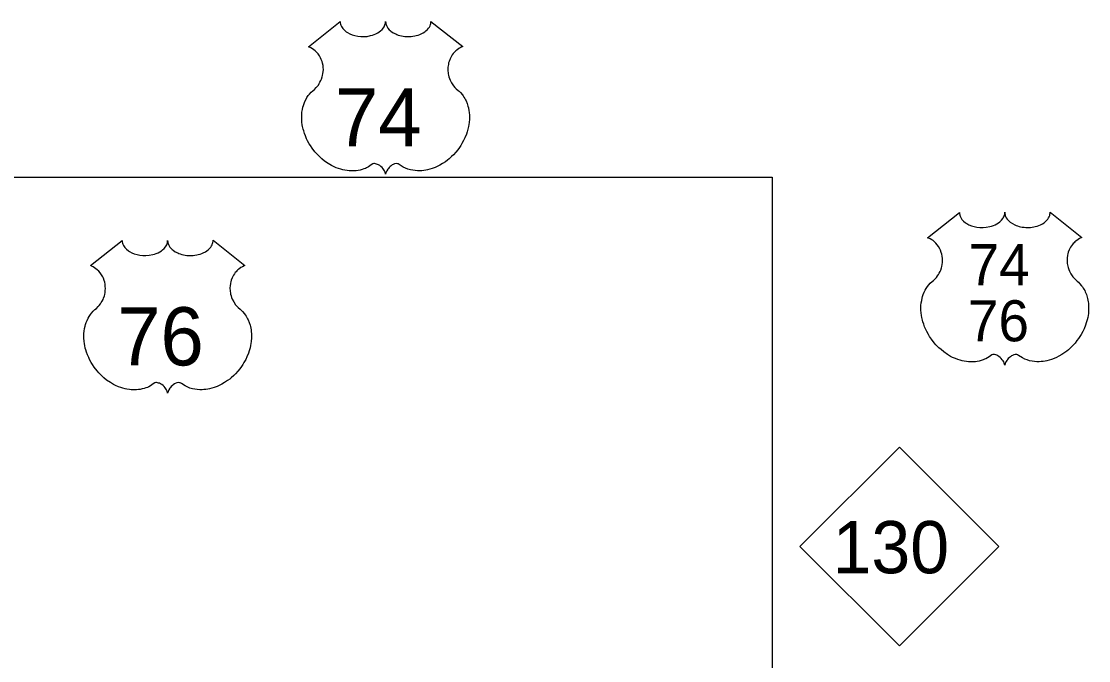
# Model space of a CAD drawing. Extents: x 5197761 to 5514561, y 1890130 to 2080942.
# Drawn here: x 5282925 to 5297224, y 2011870 to 2020438 of the extents above; entities that cross this region are included whole.
import ezdxf

# ---------------------------------------------------------------- set-up
doc = ezdxf.new("R2010")
doc.units = 0
for name, color, linetype in [('Exist Road Primary NC Shield CELL', 7, 'Continuous'), ('Exist Road Primary NC Shield Number Label', 7, 'Continuous'), ('Exist Road Primary US Shield CELL', 7, 'Continuous'), ('Exist Road Primary US Shield Number Label', 7, 'Continuous'), ('Map Preparation Inset Cut Line', 7, 'Continuous')]:
    doc.layers.add(name, color=color, linetype=linetype)

msp = doc.modelspace()

# ---------------------------------------------------------------- linework, layer by layer
at = {"layer": 'Exist Road Primary NC Shield CELL'}
msp.add_lwpolyline([(5293356, 2013399), (5294688, 2014731), (5296020, 2013399), (5294688, 2012067)], close=True, dxfattribs=at)
at = {"layer": 'Exist Road Primary US Shield CELL'}
for points in [[(5287197, 2020437), (5287198, 2020419), (5287202, 2020399), (5287205, 2020388), (5287215, 2020367), (5287231, 2020343), (5287254, 2020319), (5287279, 2020298), (5287296, 2020287), (5287325, 2020271), (5287358, 2020258), (5287395, 2020247), (5287432, 2020240), (5287473, 2020235), (5287513, 2020234), (5287557, 2020237), (5287605, 2020247), (5287628, 2020253), (5287652, 2020261), (5287676, 2020271), (5287701, 2020284), (5287721, 2020297), (5287737, 2020309), (5287760, 2020330), (5287778, 2020353), (5287785, 2020365), (5287792, 2020377), (5287801, 2020403), (5287803, 2020414), (5287805, 2020438), (5287806, 2020418), (5287808, 2020406), (5287812, 2020394), (5287817, 2020381), (5287826, 2020363), (5287836, 2020348), (5287855, 2020325), (5287867, 2020314), (5287877, 2020306), (5287906, 2020286), (5287940, 2020269), (5287957, 2020261), (5287974, 2020255), (5287995, 2020249), (5288018, 2020244), (5288040, 2020240), (5288062, 2020236), (5288085, 2020235), (5288104, 2020234), (5288127, 2020234), (5288149, 2020236), (5288171, 2020238), (5288195, 2020242), (5288214, 2020247), (5288240, 2020253), (5288263, 2020262), (5288283, 2020270), (5288309, 2020284), (5288331, 2020298), (5288346, 2020310), (5288365, 2020327), (5288382, 2020348), (5288393, 2020362), (5288400, 2020378), (5288407, 2020394), (5288411, 2020411), (5288413, 2020426), (5288413, 2020438), (5288838, 2020100), (5288828, 2020096), (5288805, 2020085), (5288787, 2020074), (5288758, 2020053), (5288745, 2020042), (5288733, 2020030), (5288721, 2020017), (5288711, 2020006), (5288699, 2019989), (5288688, 2019971), (5288677, 2019953), (5288669, 2019936), (5288656, 2019902), (5288650, 2019881), (5288646, 2019862), (5288641, 2019824), (5288639, 2019806), (5288639, 2019788), (5288640, 2019770), (5288642, 2019751), (5288645, 2019733), (5288648, 2019716), (5288654, 2019696), (5288661, 2019672), (5288670, 2019649), (5288690, 2019612), (5288715, 2019575), (5288733, 2019553), (5288750, 2019535), (5288776, 2019513), (5288791, 2019501), (5288807, 2019484), (5288834, 2019454), (5288844, 2019439), (5288855, 2019423), (5288865, 2019406), (5288875, 2019388), (5288883, 2019372), (5288898, 2019335), (5288909, 2019300), (5288914, 2019281), (5288922, 2019240), (5288925, 2019219), (5288928, 2019178), (5288929, 2019129), (5288925, 2019082), (5288916, 2019028), (5288909, 2018995), (5288898, 2018957), (5288887, 2018924), (5288867, 2018876), (5288850, 2018841), (5288828, 2018800), (5288812, 2018775), (5288795, 2018748), (5288772, 2018717), (5288746, 2018685), (5288715, 2018650), (5288689, 2018625), (5288656, 2018595), (5288636, 2018579), (5288608, 2018557), (5288568, 2018531), (5288530, 2018509), (5288497, 2018492), (5288468, 2018479), (5288430, 2018465), (5288367, 2018448), (5288345, 2018443), (5288317, 2018439), (5288292, 2018436), (5288267, 2018435), (5288234, 2018435), (5288201, 2018437), (5288170, 2018442), (5288138, 2018449), (5288104, 2018459), (5288073, 2018471), (5288042, 2018486), (5287989, 2018519), (5287974, 2018527), (5287966, 2018530), (5287945, 2018531), (5287926, 2018527), (5287907, 2018519), (5287895, 2018513), (5287879, 2018502), (5287867, 2018493), (5287853, 2018479), (5287843, 2018467), (5287835, 2018458), (5287820, 2018435), (5287815, 2018424), (5287809, 2018410), (5287805, 2018388), (5287798, 2018415), (5287790, 2018433), (5287781, 2018448), (5287772, 2018461), (5287757, 2018478), (5287743, 2018491), (5287727, 2018504), (5287710, 2018514), (5287697, 2018521), (5287684, 2018526), (5287669, 2018530), (5287656, 2018531), (5287646, 2018531), (5287632, 2018527), (5287613, 2018514), (5287594, 2018501), (5287574, 2018489), (5287551, 2018476), (5287534, 2018468), (5287513, 2018460), (5287489, 2018452), (5287463, 2018445), (5287436, 2018440), (5287412, 2018436), (5287387, 2018434), (5287364, 2018433), (5287340, 2018433), (5287318, 2018435), (5287292, 2018437), (5287260, 2018442), (5287233, 2018448), (5287205, 2018456), (5287176, 2018465), (5287145, 2018477), (5287107, 2018493), (5287080, 2018507), (5287037, 2018532), (5286988, 2018566), (5286950, 2018596), (5286923, 2018621), (5286882, 2018662), (5286859, 2018689), (5286821, 2018738), (5286797, 2018773), (5286782, 2018798), (5286759, 2018839), (5286747, 2018865), (5286731, 2018903), (5286718, 2018937), (5286708, 2018970), (5286702, 2018991), (5286694, 2019027), (5286689, 2019053), (5286684, 2019089), (5286682, 2019126), (5286681, 2019160), (5286682, 2019189), (5286685, 2019222), (5286691, 2019258), (5286698, 2019288), (5286704, 2019310), (5286713, 2019337), (5286725, 2019366), (5286739, 2019394), (5286752, 2019418), (5286769, 2019443), (5286786, 2019464), (5286808, 2019488), (5286830, 2019509), (5286851, 2019526), (5286875, 2019550), (5286888, 2019565), (5286904, 2019585), (5286916, 2019604), (5286926, 2019621), (5286939, 2019646), (5286946, 2019664), (5286956, 2019693), (5286961, 2019713), (5286966, 2019739), (5286969, 2019763), (5286971, 2019794), (5286970, 2019819), (5286967, 2019848), (5286961, 2019876), (5286955, 2019901), (5286944, 2019929), (5286934, 2019950), (5286918, 2019977), (5286900, 2020003), (5286881, 2020024), (5286862, 2020043), (5286844, 2020057), (5286827, 2020070), (5286805, 2020083), (5286785, 2020093), (5286772, 2020098)], [(5295492, 2017878), (5295493, 2017861), (5295498, 2017840), (5295501, 2017829), (5295511, 2017808), (5295527, 2017784), (5295549, 2017760), (5295575, 2017739), (5295592, 2017728), (5295621, 2017713), (5295653, 2017699), (5295690, 2017688), (5295728, 2017681), (5295768, 2017676), (5295809, 2017675), (5295853, 2017679), (5295901, 2017688), (5295923, 2017694), (5295948, 2017702), (5295971, 2017712), (5295996, 2017725), (5296017, 2017738), (5296033, 2017750), (5296055, 2017772), (5296073, 2017794), (5296081, 2017807), (5296087, 2017819), (5296096, 2017844), (5296099, 2017856), (5296101, 2017879), (5296102, 2017859), (5296104, 2017847), (5296107, 2017835), (5296112, 2017822), (5296121, 2017804), (5296131, 2017789), (5296150, 2017767), (5296162, 2017756), (5296173, 2017747), (5296202, 2017727), (5296236, 2017710), (5296252, 2017703), (5296269, 2017697), (5296291, 2017690), (5296313, 2017685), (5296335, 2017681), (5296358, 2017678), (5296381, 2017676), (5296400, 2017675), (5296423, 2017676), (5296444, 2017677), (5296466, 2017679), (5296490, 2017683), (5296509, 2017688), (5296535, 2017694), (5296558, 2017703), (5296579, 2017712), (5296605, 2017725), (5296626, 2017739), (5296642, 2017751), (5296660, 2017768), (5296678, 2017789), (5296688, 2017804), (5296696, 2017819), (5296702, 2017835), (5296706, 2017852), (5296708, 2017867), (5296709, 2017879), (5297134, 2017541), (5297124, 2017537), (5297101, 2017526), (5297083, 2017515), (5297053, 2017494), (5297041, 2017483), (5297028, 2017471), (5297017, 2017459), (5297006, 2017447), (5296994, 2017430), (5296983, 2017413), (5296972, 2017394), (5296964, 2017377), (5296951, 2017343), (5296945, 2017322), (5296941, 2017303), (5296936, 2017265), (5296935, 2017247), (5296935, 2017230), (5296936, 2017211), (5296938, 2017193), (5296941, 2017174), (5296944, 2017157), (5296949, 2017137), (5296957, 2017113), (5296966, 2017090), (5296985, 2017053), (5297010, 2017016), (5297028, 2016995), (5297046, 2016977), (5297072, 2016954), (5297086, 2016942), (5297102, 2016926), (5297129, 2016895), (5297140, 2016880), (5297151, 2016864), (5297161, 2016847), (5297171, 2016829), (5297179, 2016813), (5297194, 2016777), (5297205, 2016741), (5297210, 2016723), (5297218, 2016681), (5297221, 2016660), (5297224, 2016620), (5297224, 2016570), (5297220, 2016524), (5297212, 2016469), (5297204, 2016437), (5297193, 2016399), (5297182, 2016366), (5297163, 2016317), (5297146, 2016282), (5297123, 2016241), (5297108, 2016216), (5297090, 2016189), (5297068, 2016159), (5297042, 2016126), (5297010, 2016092), (5296985, 2016066), (5296952, 2016037), (5296932, 2016020), (5296903, 2015998), (5296864, 2015972), (5296825, 2015950), (5296792, 2015933), (5296763, 2015921), (5296726, 2015906), (5296663, 2015889), (5296640, 2015884), (5296613, 2015880), (5296588, 2015878), (5296563, 2015876), (5296530, 2015876), (5296497, 2015879), (5296466, 2015883), (5296433, 2015890), (5296400, 2015900), (5296369, 2015912), (5296338, 2015927), (5296285, 2015960), (5296270, 2015969), (5296261, 2015971), (5296241, 2015972), (5296222, 2015968), (5296202, 2015960), (5296191, 2015954), (5296175, 2015943), (5296163, 2015934), (5296148, 2015920), (5296138, 2015908), (5296131, 2015899), (5296116, 2015876), (5296110, 2015865), (5296105, 2015851), (5296100, 2015830), (5296093, 2015856), (5296086, 2015874), (5296077, 2015889), (5296067, 2015902), (5296052, 2015919), (5296039, 2015932), (5296023, 2015945), (5296006, 2015955), (5295992, 2015962), (5295980, 2015967), (5295964, 2015971), (5295952, 2015972), (5295941, 2015972), (5295927, 2015969), (5295908, 2015955), (5295890, 2015942), (5295870, 2015930), (5295846, 2015917), (5295829, 2015909), (5295809, 2015901), (5295784, 2015893), (5295758, 2015886), (5295731, 2015881), (5295708, 2015877), (5295682, 2015875), (5295660, 2015874), (5295636, 2015875), (5295613, 2015876), (5295588, 2015879), (5295555, 2015883), (5295529, 2015889), (5295501, 2015897), (5295472, 2015906), (5295441, 2015918), (5295402, 2015935), (5295375, 2015948), (5295333, 2015973), (5295283, 2016007), (5295246, 2016038), (5295218, 2016062), (5295178, 2016104), (5295154, 2016131), (5295117, 2016179), (5295093, 2016214), (5295078, 2016239), (5295055, 2016281), (5295043, 2016306), (5295026, 2016344), (5295014, 2016378), (5295003, 2016411), (5294998, 2016432), (5294990, 2016468), (5294985, 2016494), (5294980, 2016530), (5294977, 2016567), (5294977, 2016602), (5294978, 2016630), (5294981, 2016664), (5294987, 2016699), (5294993, 2016729), (5294999, 2016751), (5295009, 2016778), (5295020, 2016807), (5295034, 2016835), (5295048, 2016859), (5295065, 2016884), (5295081, 2016905), (5295103, 2016929), (5295126, 2016950), (5295146, 2016967), (5295171, 2016991), (5295184, 2017006), (5295199, 2017026), (5295212, 2017045), (5295221, 2017062), (5295234, 2017087), (5295242, 2017105), (5295252, 2017134), (5295257, 2017154), (5295262, 2017180), (5295265, 2017204), (5295266, 2017235), (5295265, 2017260), (5295262, 2017289), (5295257, 2017317), (5295250, 2017342), (5295239, 2017370), (5295230, 2017391), (5295214, 2017419), (5295195, 2017445), (5295177, 2017466), (5295158, 2017484), (5295140, 2017499), (5295123, 2017511), (5295101, 2017524), (5295080, 2017534), (5295067, 2017539)], [(5284277, 2017502), (5284278, 2017485), (5284282, 2017464), (5284286, 2017453), (5284295, 2017433), (5284312, 2017408), (5284334, 2017384), (5284359, 2017363), (5284376, 2017352), (5284405, 2017337), (5284438, 2017323), (5284475, 2017312), (5284512, 2017305), (5284553, 2017300), (5284594, 2017300), (5284637, 2017303), (5284686, 2017312), (5284708, 2017318), (5284733, 2017327), (5284756, 2017336), (5284781, 2017350), (5284802, 2017363), (5284818, 2017374), (5284840, 2017396), (5284858, 2017418), (5284866, 2017431), (5284872, 2017443), (5284881, 2017468), (5284884, 2017480), (5284885, 2017503), (5284887, 2017484), (5284889, 2017471), (5284892, 2017459), (5284897, 2017446), (5284906, 2017428), (5284916, 2017413), (5284935, 2017391), (5284947, 2017380), (5284958, 2017371), (5284987, 2017351), (5285020, 2017334), (5285037, 2017327), (5285054, 2017321), (5285076, 2017314), (5285098, 2017309), (5285120, 2017305), (5285143, 2017302), (5285166, 2017300), (5285185, 2017300), (5285208, 2017300), (5285229, 2017301), (5285251, 2017304), (5285275, 2017308), (5285294, 2017312), (5285320, 2017319), (5285343, 2017327), (5285363, 2017336), (5285390, 2017350), (5285411, 2017363), (5285427, 2017375), (5285445, 2017393), (5285463, 2017413), (5285473, 2017428), (5285480, 2017443), (5285487, 2017459), (5285491, 2017476), (5285493, 2017491), (5285494, 2017504), (5285919, 2017165), (5285909, 2017161), (5285886, 2017150), (5285867, 2017139), (5285838, 2017119), (5285826, 2017107), (5285813, 2017095), (5285801, 2017083), (5285791, 2017071), (5285779, 2017054), (5285768, 2017037), (5285757, 2017018), (5285749, 2017002), (5285736, 2016968), (5285730, 2016946), (5285726, 2016928), (5285721, 2016890), (5285720, 2016872), (5285720, 2016854), (5285721, 2016835), (5285722, 2016817), (5285726, 2016798), (5285729, 2016781), (5285734, 2016761), (5285741, 2016737), (5285751, 2016715), (5285770, 2016678), (5285795, 2016640), (5285813, 2016619), (5285831, 2016601), (5285857, 2016579), (5285871, 2016566), (5285887, 2016550), (5285914, 2016519), (5285925, 2016504), (5285936, 2016488), (5285946, 2016471), (5285956, 2016453), (5285964, 2016437), (5285979, 2016401), (5285990, 2016365), (5285995, 2016347), (5286003, 2016305), (5286006, 2016285), (5286009, 2016244), (5286009, 2016195), (5286005, 2016148), (5285996, 2016093), (5285989, 2016061), (5285978, 2016023), (5285967, 2015990), (5285948, 2015941), (5285931, 2015906), (5285908, 2015865), (5285893, 2015840), (5285875, 2015814), (5285853, 2015783), (5285827, 2015750), (5285795, 2015716), (5285770, 2015690), (5285737, 2015661), (5285717, 2015644), (5285688, 2015623), (5285649, 2015597), (5285610, 2015574), (5285577, 2015557), (5285548, 2015545), (5285510, 2015530), (5285448, 2015513), (5285425, 2015508), (5285398, 2015504), (5285372, 2015502), (5285348, 2015500), (5285315, 2015500), (5285282, 2015503), (5285251, 2015507), (5285218, 2015514), (5285184, 2015524), (5285154, 2015536), (5285122, 2015552), (5285070, 2015585), (5285055, 2015593), (5285046, 2015595), (5285026, 2015596), (5285007, 2015592), (5284987, 2015584), (5284975, 2015578), (5284960, 2015568), (5284948, 2015558), (5284933, 2015544), (5284923, 2015533), (5284915, 2015524), (5284901, 2015500), (5284895, 2015489), (5284890, 2015475), (5284885, 2015454), (5284878, 2015480), (5284870, 2015498), (5284861, 2015513), (5284852, 2015526), (5284837, 2015544), (5284824, 2015556), (5284808, 2015569), (5284791, 2015580), (5284777, 2015587), (5284764, 2015591), (5284749, 2015595), (5284737, 2015596), (5284726, 2015596), (5284712, 2015593), (5284693, 2015579), (5284675, 2015566), (5284655, 2015554), (5284631, 2015541), (5284614, 2015533), (5284593, 2015525), (5284569, 2015517), (5284543, 2015511), (5284516, 2015505), (5284493, 2015502), (5284467, 2015499), (5284444, 2015499), (5284421, 2015499), (5284398, 2015501), (5284372, 2015503), (5284340, 2015508), (5284314, 2015514), (5284286, 2015521), (5284257, 2015530), (5284226, 2015542), (5284187, 2015559), (5284160, 2015573), (5284118, 2015597), (5284068, 2015631), (5284031, 2015662), (5284003, 2015687), (5283963, 2015728), (5283939, 2015755), (5283902, 2015803), (5283878, 2015838), (5283862, 2015864), (5283840, 2015905), (5283827, 2015931), (5283811, 2015968), (5283799, 2016003), (5283788, 2016035), (5283782, 2016056), (5283774, 2016093), (5283769, 2016118), (5283765, 2016154), (5283762, 2016191), (5283762, 2016226), (5283762, 2016254), (5283766, 2016288), (5283771, 2016323), (5283778, 2016354), (5283784, 2016375), (5283793, 2016402), (5283805, 2016431), (5283819, 2016460), (5283833, 2016483), (5283850, 2016508), (5283866, 2016529), (5283888, 2016553), (5283910, 2016575), (5283931, 2016591), (5283956, 2016616), (5283969, 2016630), (5283984, 2016651), (5283996, 2016669), (5284006, 2016686), (5284019, 2016711), (5284027, 2016730), (5284037, 2016758), (5284042, 2016778), (5284047, 2016804), (5284050, 2016829), (5284051, 2016859), (5284050, 2016884), (5284047, 2016914), (5284042, 2016942), (5284035, 2016966), (5284024, 2016994), (5284015, 2017015), (5283998, 2017043), (5283980, 2017069), (5283962, 2017090), (5283943, 2017109), (5283925, 2017123), (5283907, 2017135), (5283886, 2017148), (5283865, 2017158), (5283852, 2017164)]]:
    msp.add_lwpolyline(points, close=True, dxfattribs=at)
at = {"layer": 'Map Preparation Inset Cut Line'}
msp.add_lwpolyline([(5275692, 2018349), (5292986, 2018349), (5292986, 2003094), (5275692, 2003094)], close=True, dxfattribs=at)

# ---------------------------------------------------------------- texts
at = {"layer": 'Exist Road Primary NC Shield Number Label'}
msp.add_text('130', height=700, dxfattribs=at).set_placement((5293793, 2013041))
at = {"layer": 'Exist Road Primary US Shield Number Label'}
for s, height, p in [('74', 780, (5287128, 2018762)), ('74', 550, (5295616, 2016902)), ('76', 780, (5284209, 2015827)), ('76', 550, (5295607, 2016150))]:
    msp.add_text(s, height=height, dxfattribs=at).set_placement(p)

doc.saveas('drawing.dxf')
